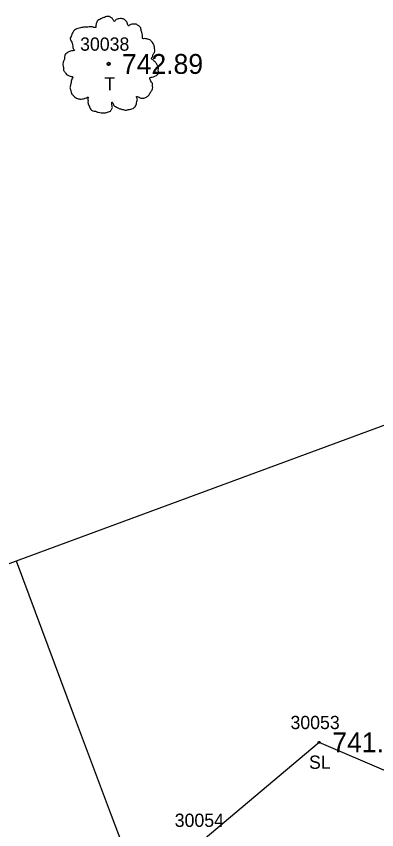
# Model space of a CAD drawing. Extents: x 1375131 to 1378678, y 999028 to 1004053.
# Drawn here: x 1376809.2 to 1376836.5, y 1002721.2 to 1002782.6 of the extents above; entities that cross this region are included whole.
import ezdxf

# ---------------------------------------------------------------- set-up
doc = ezdxf.new("R2010")
doc.units = 0
for name, color, linetype in [('RD_EX_Road', 7, 'Continuous'), ('RD_EX_RW', 7, 'Continuous'), ('RD_EX_TX_VEG_ELEV', 7, 'Continuous'), ('RD_EX_VEG', 7, 'Continuous'), ('RD_EX_VEG_txCode', 7, 'Continuous'), ('RD_HC_Cl', 7, 'Continuous'), ('RD_HC_Data', 7, 'Continuous'), ('RD_SMD_Locator', 7, 'Continuous')]:
    doc.layers.add(name, color=color, linetype=linetype)

msp = doc.modelspace()

# ---------------------------------------------------------------- linework, layer by layer
at = {"layer": 'RD_EX_Road'}
for points in [[(1377013.314, 1002264.907), (1376982.808, 1002315.683), (1376952.468, 1002370.341), (1376923.174, 1002424.32), (1376895.644, 1002480.03), (1376870.11, 1002535.049), (1376846.329, 1002588.864), (1376822.292, 1002645.031), (1376786.564, 1002736.458)], [(1376994.747, 1002253.913), (1376964.909, 1002306.463), (1376934.396, 1002359.987), (1376904.773, 1002415.485), (1376877.271, 1002471.511), (1376851.037, 1002526.893), (1376827.48, 1002581.62), (1376804.191, 1002637.821), (1376768.457, 1002728.838)]]:
    msp.add_spline(points, degree=3, dxfattribs=at)
at = {"layer": 'RD_EX_RW'}
msp.add_arc((1379404.86, 1003700.108), 2767, 200.269954, 211.131166, dxfattribs=at)
at = {"layer": 'RD_EX_VEG'}
msp.add_lwpolyline([(1376842.762, 1002723.226), (1376832.093, 1002727.803), (1376823.348, 1002720.418), (1376822.468, 1002711.668), (1376833.651, 1002706.033), (1376840.672, 1002709.675), (1376845.16, 1002718.521), (1376843.119, 1002722.182)], dxfattribs=at)
for centre, radius in [((1376816.199, 1002779.024), 0.125), ((1376816.193, 1002779.015), 0.00005)]:
    msp.add_circle(centre, radius, dxfattribs=at)
for points in [[(1376816.265, 1002782.608), (1376816.115, 1002782.62), (1376815.953, 1002782.57), (1376815.828, 1002782.52), (1376815.715, 1002782.483), (1376815.603, 1002782.433), (1376815.453, 1002782.345), (1376815.34, 1002782.245), (1376815.278, 1002782.12), (1376815.253, 1002782.008), (1376815.228, 1002781.87), (1376815.228, 1002781.783), (1376815.165, 1002781.77), (1376815.09, 1002781.783), (1376814.966, 1002781.82), (1376814.841, 1002781.82), (1376814.716, 1002781.82), (1376814.541, 1002781.808), (1376814.366, 1002781.808), (1376814.228, 1002781.783), (1376814.066, 1002781.758), (1376813.879, 1002781.696), (1376813.704, 1002781.633), (1376813.554, 1002781.508), (1376813.429, 1002781.271), (1376813.366, 1002781.096), (1376813.291, 1002780.971), (1376813.366, 1002780.746), (1376813.454, 1002780.571), (1376813.466, 1002780.471), (1376813.504, 1002780.259), (1376813.554, 1002780.146), (1376813.616, 1002780.046), (1376813.579, 1002780.034), (1376813.391, 1002780.009), (1376813.241, 1002779.959), (1376813.029, 1002779.846), (1376812.916, 1002779.734), (1376812.866, 1002779.571), (1376812.854, 1002779.397), (1376812.804, 1002779.297), (1376812.767, 1002779.159), (1376812.754, 1002779.122), (1376812.729, 1002778.959), (1376812.779, 1002778.734), (1376812.792, 1002778.559), (1376812.854, 1002778.447), (1376812.929, 1002778.36), (1376813.016, 1002778.235), (1376813.216, 1002778.122), (1376813.379, 1002778.072), (1376813.479, 1002778.06), (1376813.391, 1002777.81), (1376813.366, 1002777.635), (1376813.304, 1002777.435), (1376813.304, 1002777.397), (1376813.279, 1002777.16), (1376813.354, 1002776.998), (1376813.391, 1002776.81), (1376813.479, 1002776.698), (1376813.616, 1002776.548), (1376813.779, 1002776.435), (1376814.028, 1002776.373), (1376814.228, 1002776.385), (1376814.516, 1002776.473), (1376814.641, 1002776.51), (1376814.628, 1002776.423), (1376814.641, 1002776.235), (1376814.641, 1002776.023), (1376814.716, 1002775.861), (1376814.766, 1002775.723), (1376814.841, 1002775.598), (1376815.003, 1002775.486), (1376815.203, 1002775.448), (1376815.415, 1002775.373), (1376815.64, 1002775.336), (1376815.89, 1002775.323), (1376816.19, 1002775.398), (1376816.327, 1002775.461), (1376816.377, 1002775.548), (1376816.477, 1002775.736), (1376816.452, 1002775.848), (1376816.465, 1002776.148), (1376816.515, 1002776.06), (1376816.602, 1002775.886), (1376816.852, 1002775.736), (1376817.052, 1002775.648), (1376817.29, 1002775.573), (1376817.439, 1002775.536), (1376817.677, 1002775.573), (1376817.864, 1002775.611), (1376818.052, 1002775.673), (1376818.202, 1002775.811), (1376818.289, 1002775.948), (1376818.314, 1002776.085), (1376818.352, 1002776.273), (1376818.377, 1002776.36)], [(1376818.377, 1002776.36), (1376818.339, 1002776.448), (1376818.314, 1002776.573), (1376818.352, 1002776.56), (1376818.439, 1002776.535), (1376818.576, 1002776.473), (1376818.689, 1002776.435), (1376818.851, 1002776.448), (1376818.989, 1002776.498), (1376819.214, 1002776.635), (1376819.351, 1002776.873), (1376819.489, 1002777.073), (1376819.526, 1002777.235), (1376819.501, 1002777.347), (1376819.489, 1002777.597), (1376819.389, 1002777.722), (1376819.364, 1002777.785), (1376819.314, 1002777.985), (1376819.351, 1002778.01), (1376819.489, 1002778.035), (1376819.676, 1002778.097), (1376819.813, 1002778.16), (1376819.926, 1002778.247), (1376819.963, 1002778.36), (1376819.951, 1002778.559), (1376819.976, 1002778.759), (1376819.938, 1002778.834), (1376819.888, 1002778.909), (1376819.851, 1002779.009), (1376819.776, 1002779.084), (1376819.726, 1002779.159), (1376819.676, 1002779.209), (1376819.614, 1002779.284), (1376819.526, 1002779.347), (1376819.451, 1002779.372), (1376819.426, 1002779.447), (1376819.501, 1002779.546), (1376819.526, 1002779.596), (1376819.539, 1002779.709), (1376819.651, 1002779.884), (1376819.676, 1002780.084), (1376819.651, 1002780.296), (1376819.626, 1002780.434), (1376819.551, 1002780.571), (1376819.451, 1002780.696), (1376819.389, 1002780.783), (1376819.301, 1002780.846), (1376819.139, 1002780.908), (1376819.014, 1002780.933), (1376818.839, 1002780.933), (1376818.739, 1002780.958), (1376818.751, 1002780.983), (1376818.751, 1002781.058), (1376818.751, 1002781.196), (1376818.714, 1002781.421), (1376818.639, 1002781.671), (1376818.639, 1002781.683), (1376818.589, 1002781.808), (1376818.477, 1002781.908), (1376818.389, 1002781.958), (1376818.289, 1002782.02), (1376818.164, 1002782.033), (1376818.014, 1002782.033), (1376817.877, 1002782.008), (1376817.777, 1002781.958), (1376817.689, 1002781.895), (1376817.652, 1002781.97), (1376817.602, 1002782.12), (1376817.577, 1002782.195), (1376817.502, 1002782.283), (1376817.39, 1002782.383), (1376817.165, 1002782.445), (1376816.852, 1002782.408), (1376816.702, 1002782.308), (1376816.627, 1002782.22), (1376816.602, 1002782.283), (1376816.502, 1002782.383), (1376816.452, 1002782.47), (1376816.365, 1002782.533), (1376816.29, 1002782.583), (1376816.24, 1002782.608)]]:
    msp.add_spline(points, degree=3, dxfattribs=at)
at = {"layer": 'RD_HC_Cl'}
msp.add_arc((1379404.86, 1003700.108), 2800, 200.269954, 211.131166, dxfattribs=at)
at = {"layer": 'RD_HC_Data'}
msp.add_line((1376778.262, 1002730.065), (1376911.622, 1002779.317), dxfattribs=at)
at = {"layer": 'RD_SMD_Locator'}
for centre in [(1376816.199, 1002779.024), (1376832.093, 1002727.803)]:
    msp.add_circle(centre, 0.075, dxfattribs=at)

# ---------------------------------------------------------------- texts
at = {"layer": 'RD_EX_TX_VEG_ELEV'}
for s, p in [('742.89', (1376817.199, 1002778.274)), ('741.08', (1376833.093, 1002727.053))]:
    msp.add_text(s, height=1.5, dxfattribs=at).set_placement(p)
at = {"layer": 'RD_EX_VEG_txCode'}
for s, p in [('30038', (1376814.042, 1002780.024)), ('T', (1376815.876, 1002777.024)), ('30053', (1376829.936, 1002728.803)), ('SL', (1376831.337, 1002725.803)), ('30054', (1376821.191, 1002721.418))]:
    msp.add_text(s, height=1, dxfattribs=at).set_placement(p)

doc.saveas('drawing.dxf')
